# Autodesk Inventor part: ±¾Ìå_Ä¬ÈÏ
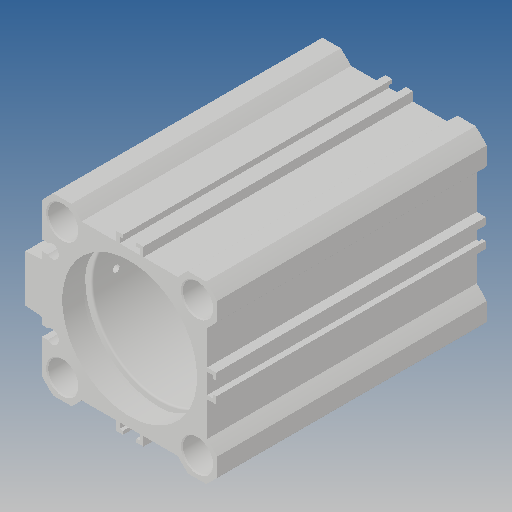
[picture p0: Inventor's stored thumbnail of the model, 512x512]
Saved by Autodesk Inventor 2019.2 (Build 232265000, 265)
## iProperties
Created: 2011-12
Part Number: ±¾Ìå_Ä¬ÈÏ
Material: Ogólny
Document SubType Name: Modeling
Designer: CADENGINEERING4
Density: 1 g/cm^3
Appearance: Domyślna
Author: CADENGINEERING4
Revision Number: ÈÎºÎ
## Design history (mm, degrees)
feature "NONE"
node "Bryła1"
